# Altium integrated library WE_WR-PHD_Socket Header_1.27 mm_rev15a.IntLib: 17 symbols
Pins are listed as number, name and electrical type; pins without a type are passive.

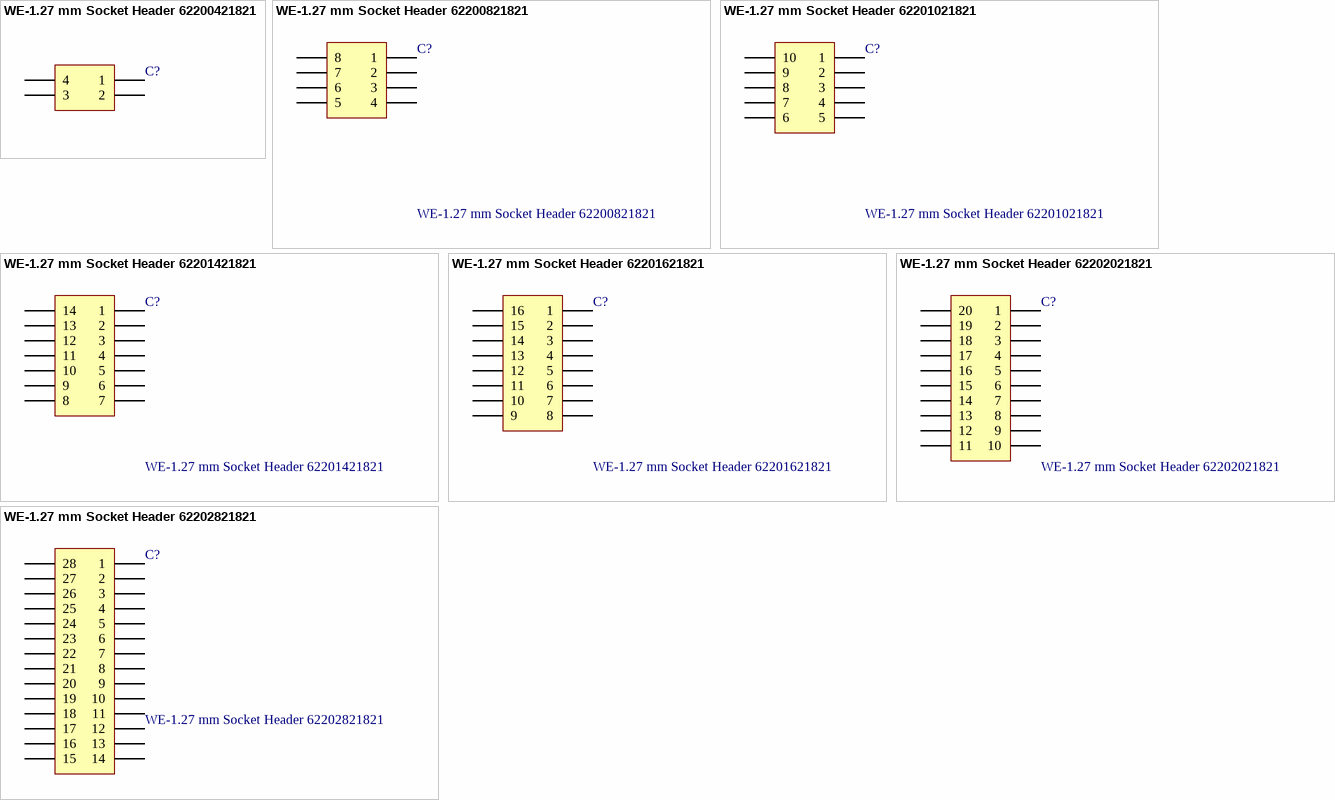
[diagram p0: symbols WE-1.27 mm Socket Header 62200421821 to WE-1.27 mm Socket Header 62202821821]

## WE-1.27 mm Socket Header 62200421821
designator C?
WR-PHD 1.27 mm Dual Socket Header; Manufacturer: Würth Elektronik eiSos GmbH; ComponentLink1 Description: Manufacturer; ComponentLink2 Description: Datasheet; NoPins: 04
footprint 62200421821 (4 pins, dual row, straight, gold plating)
pins: 1, 2, 3, 4

## WE-1.27 mm Socket Header 62200821821
designator C?
WR-PHD 1.27 mm Dual Socket Header; Manufacturer: Würth Elektronik eiSos GmbH; ComponentLink1 Description: Manufacturer; ComponentLink2 Description: Datasheet; NoPins: 08
footprint 62200821821 (8 pins, dual row, straight, gold plating)
pins: 1, 2, 3, 4, 5, 6, 7, 8

## WE-1.27 mm Socket Header 62201021821
designator C?
WR-PHD 1.27 mm Dual Socket Header; Manufacturer: Würth Elektronik eiSos GmbH; ComponentLink1 Description: Manufacturer; ComponentLink2 Description: Datasheet; NoPins: 10
footprint 62201021821 (10 pins, dual row, straight, gold plating)
pins: 1, 2, 3, 4, 5, 6, 7, 8, 9, 10

## WE-1.27 mm Socket Header 62201421821
designator C?
WR-PHD 1.27 mm Dual Socket Header; Manufacturer: Würth Elektronik eiSos GmbH; ComponentLink1 Description: Manufacturer; ComponentLink2 Description: Datasheet; NoPins: 14
footprint 62201421821 (14 pins, dual row, straight, gold plating)
pins: 1, 2, 3, 4, 5, 6, 7, 8, 9, 10, 11, 12, 13, 14

## WE-1.27 mm Socket Header 62201621821
designator C?
WR-PHD 1.27 mm Dual Socket Header; Manufacturer: Würth Elektronik eiSos GmbH; ComponentLink1 Description: Manufacturer; ComponentLink2 Description: Datasheet; NoPins: 16
footprint 62201621821 (16 pins, dual row, straight, gold plating)
pins: 1, 2, 3, 4, 5, 6, 7, 8, 9, 10, 11, 12, 13, 14, 15, 16

## WE-1.27 mm Socket Header 62202021821
designator C?
WR-PHD 1.27 mm Dual Socket Header; Manufacturer: Würth Elektronik eiSos GmbH; ComponentLink1 Description: Manufacturer; ComponentLink2 Description: Datasheet; NoPins: 20
footprint 62202021821 (20 pins, dual row, straight, gold plating)
pins: 1, 2, 3, 4, 5, 6, 7, 8, 9, 10, 11, 12, 13, 14, 15, 16, 17, 18, 19, 20

## WE-1.27 mm Socket Header 62202821821
designator C?
WR-PHD 1.27 mm Dual Socket Header; Manufacturer: Würth Elektronik eiSos GmbH; ComponentLink1 Description: Manufacturer; ComponentLink2 Description: Datasheet; NoPins: 28
footprint 62202821821 (28 pins, dual row, straight, gold plating)
pins: 1, 2, 3, 4, 5, 6, 7, 8, 9, 10, 11, 12, 13, 14, 15, 16, 17, 18, 19, 20, 21, 22, 23, 24, 25, 26, 27, 28


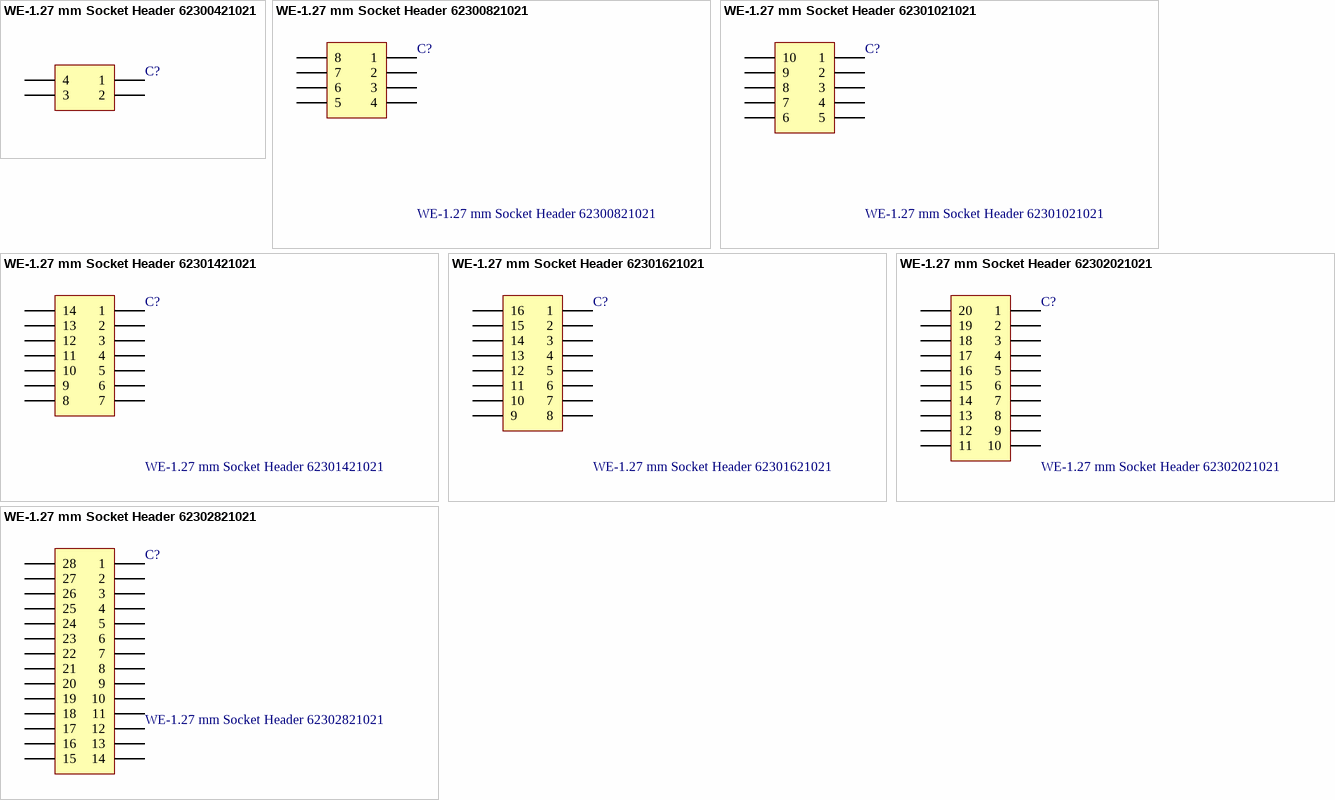
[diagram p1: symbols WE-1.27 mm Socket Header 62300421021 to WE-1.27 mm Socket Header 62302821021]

## WE-1.27 mm Socket Header 62300421021
designator C?
WR-PHD 1.27 mm Dual SMT Socket Header H=4.50mm; Manufacturer: Würth Elektronik eiSos GmbH; ComponentLink1 Description: Manufacturer; ComponentLink2 Description: Datasheet; NoPins: 04
footprint 62300421021 (4 pins, dual row, straight, gold plating)
pins: 1, 2, 3, 4

## WE-1.27 mm Socket Header 62300821021
designator C?
WR-PHD 1.27 mm Dual SMT Socket Header H=4.50mm; Manufacturer: Würth Elektronik eiSos GmbH; ComponentLink1 Description: Manufacturer; ComponentLink2 Description: Datasheet; NoPins: 08
footprint 62300821021 (8 pins, dual row, straight, gold plating)
pins: 1, 2, 3, 4, 5, 6, 7, 8

## WE-1.27 mm Socket Header 62301021021
designator C?
WR-PHD 1.27 mm Dual SMT Socket Header H=4.50mm; Manufacturer: Würth Elektronik eiSos GmbH; ComponentLink1 Description: Manufacturer; ComponentLink2 Description: Datasheet; NoPins: 10
footprint 62301021021 (10 pins, dual row, straight, gold plating)
pins: 1, 2, 3, 4, 5, 6, 7, 8, 9, 10

## WE-1.27 mm Socket Header 62301421021
designator C?
WR-PHD 1.27 mm Dual SMT Socket Header H=4.50mm; Manufacturer: Würth Elektronik eiSos GmbH; ComponentLink1 Description: Manufacturer; ComponentLink2 Description: Datasheet; NoPins: 14
footprint 62301421021 (14 pins, dual row, straight, gold plating)
pins: 1, 2, 3, 4, 5, 6, 7, 8, 9, 10, 11, 12, 13, 14

## WE-1.27 mm Socket Header 62301621021
designator C?
WR-PHD 1.27 mm Dual SMT Socket Header H=4.50mm; Manufacturer: Würth Elektronik eiSos GmbH; ComponentLink1 Description: Manufacturer; ComponentLink2 Description: Datasheet; NoPins: 16
footprint 62301621021 (16 pins, dual row, straight, gold plating)
pins: 1, 2, 3, 4, 5, 6, 7, 8, 9, 10, 11, 12, 13, 14, 15, 16

## WE-1.27 mm Socket Header 62302021021
designator C?
WR-PHD 1.27 mm Dual SMT Socket Header H=4.50mm; Manufacturer: Würth Elektronik eiSos GmbH; ComponentLink1 Description: Manufacturer; ComponentLink2 Description: Datasheet; NoPins: 20
footprint 62302021021 (20 pins, dual row, straight, gold plating)
pins: 1, 2, 3, 4, 5, 6, 7, 8, 9, 10, 11, 12, 13, 14, 15, 16, 17, 18, 19, 20

## WE-1.27 mm Socket Header 62302821021
designator C?
WR-PHD 1.27 mm Dual SMT Socket Header H=4.50mm; Manufacturer: Würth Elektronik eiSos GmbH; ComponentLink1 Description: Manufacturer; ComponentLink2 Description: Datasheet; NoPins: 28
footprint 62302821021 (28 pins, dual row, straight, gold plating)
pins: 1, 2, 3, 4, 5, 6, 7, 8, 9, 10, 11, 12, 13, 14, 15, 16, 17, 18, 19, 20, 21, 22, 23, 24, 25, 26, 27, 28


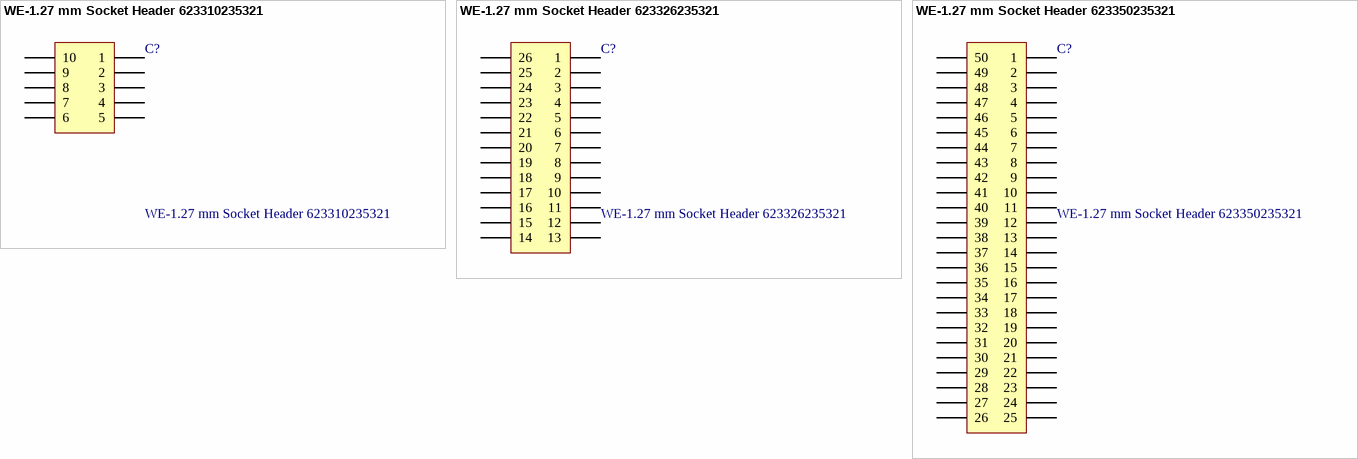
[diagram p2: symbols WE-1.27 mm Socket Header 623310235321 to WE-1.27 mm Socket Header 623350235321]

## WE-1.27 mm Socket Header 623310235321
designator C?
WR-PHD 1.27 mm Dual SMT Socket Header H=2.20mm; Manufacturer: Würth Elektronik eiSos GmbH; ComponentLink1 Description: Manufacturer; ComponentLink2 Description: Datasheet; NoPins: 10
footprint 623310235321 (10 pins, dual row, straight, gold plating)
pins: 1, 2, 3, 4, 5, 6, 7, 8, 9, 10

## WE-1.27 mm Socket Header 623326235321
designator C?
WR-PHD 1.27 mm Dual SMT Socket Header H=2.20mm; Manufacturer: Würth Elektronik eiSos GmbH; ComponentLink1 Description: Manufacturer; ComponentLink2 Description: Datasheet; NoPins: 26
footprint 623326235321 (26 pins, dual row, straight, gold plating)
pins: 1, 2, 3, 4, 5, 6, 7, 8, 9, 10, 11, 12, 13, 14, 15, 16, 17, 18, 19, 20, 21, 22, 23, 24, 25, 26

## WE-1.27 mm Socket Header 623350235321
designator C?
WR-PHD 1.27 mm Dual SMT Socket Header H=2.20mm; Manufacturer: Würth Elektronik eiSos GmbH; ComponentLink1 Description: Manufacturer; ComponentLink2 Description: Datasheet; NoPins: 50
footprint 623350235321 (50 pins, dual row, straight, gold plating)
pins: 1, 2, 3, 4, 5, 6, 7, 8, 9, 10, 11, 12, 13, 14, 15, 16, 17, 18, 19, 20, 21, 22, 23, 24, 25, 26, 27, 28, 29, 30, 31, 32, 33, 34, 35, 36, 37, 38, 39, 40, 41, 42, 43, 44, 45, 46, 47, 48, 49, 50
